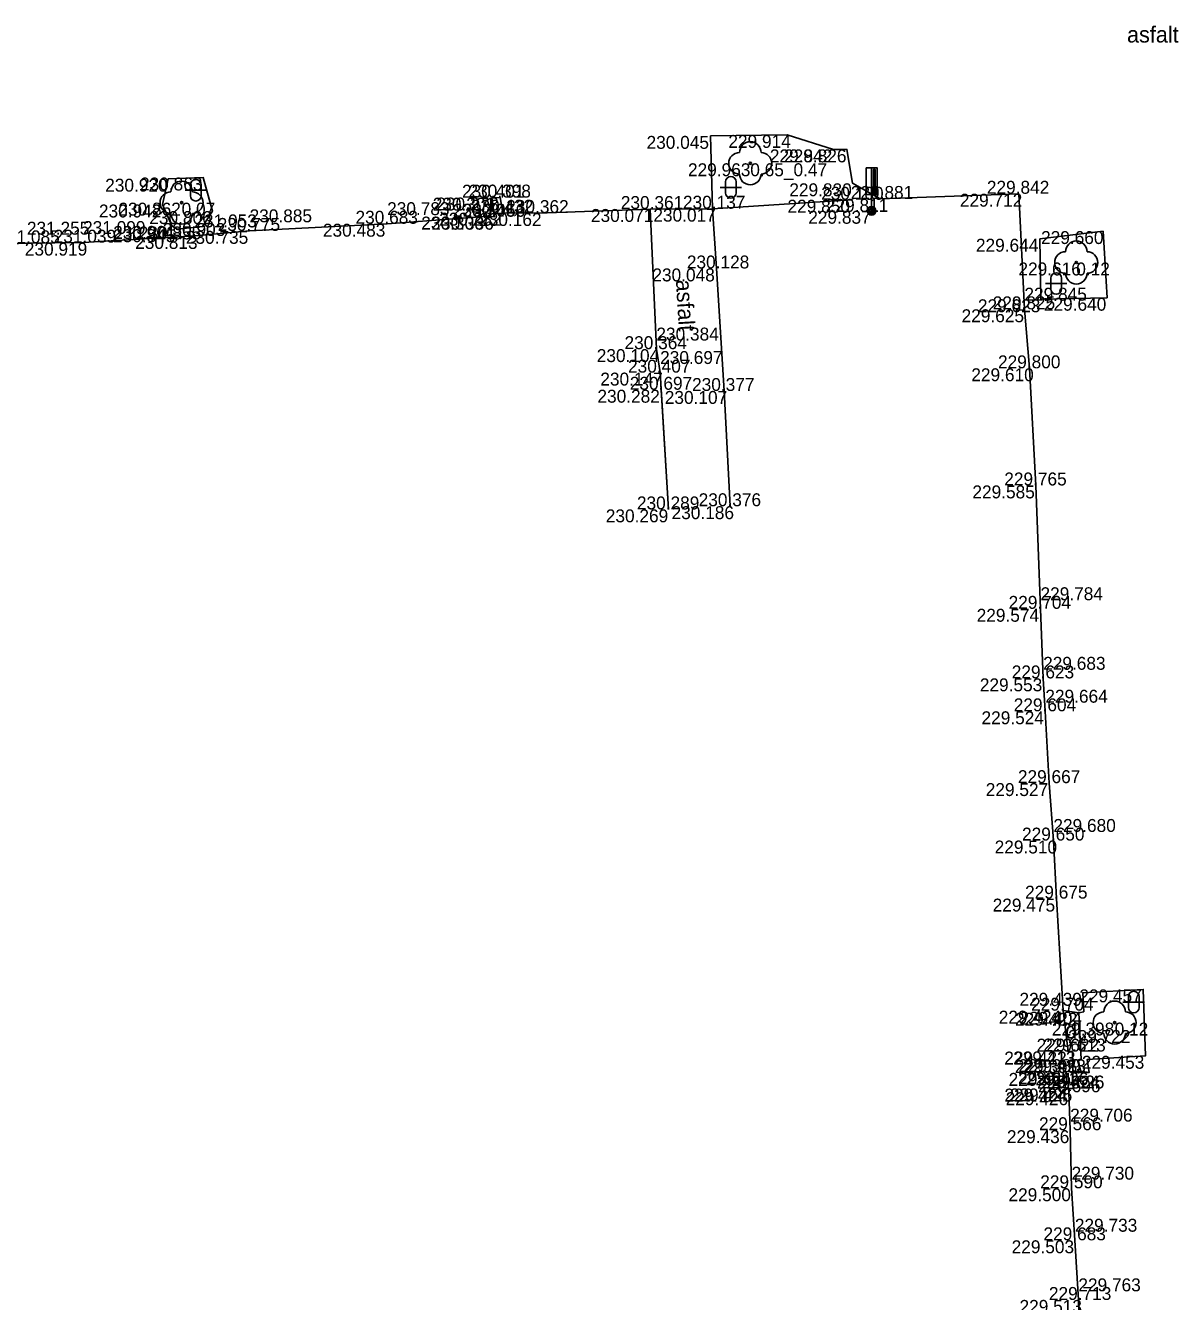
# Model space of a CAD drawing. Extents: x -599516 to -599132, y -1163668 to -1163119.
# Drawn here: x -599458.95 to -599432.17, y -1163270.22 to -1163240.6 of the extents above; entities that cross this region are included whole.
import ezdxf

# ---------------------------------------------------------------- set-up
doc = ezdxf.new("R2010")
doc.units = 0
for name, color, linetype in [('Bod-oznac1', 7, 'Continuous'), ('Bod-oznac2', 7, 'Continuous'), ('Bod-oznac3', 7, 'Continuous'), ('Bod-vyska1', 7, 'Continuous'), ('Bod-vyska2', 7, 'Continuous'), ('Bod-vyska3', 7, 'Continuous'), ('Z_cela-hrobu-dolni-linie', 7, 'Continuous'), ('Z_cela-hrobu-horni-linie', 7, 'Continuous'), ('Z_chodnik', 7, 'Continuous'), ('Z_komunikace', 7, 'Continuous'), ('Z_kultury-znacky', 7, 'Continuous'), ('Z_nove-stromy-prumer-kmene', 7, 'Continuous'), ('Z_obvod-kmene-spodek-ve-vysce1_2m', 7, 'Continuous'), ('Z_popis-budov-povrchu', 7, 'Continuous'), ('Z_stromy-kere', 7, 'Continuous'), ('Z_stromy-nove-vysazene', 7, 'Continuous'), ('Z_terenni-hrana', 7, 'Continuous'), ('Z_znacky-ostatni-orientacni-sloupek', 7, 'Continuous'), ('Z_zpevnene-plochy', 7, 'Continuous')]:
    doc.layers.add(name, color=color, linetype=linetype)

msp = doc.modelspace()

# ---------------------------------------------------------------- linework, layer by layer
at = {"layer": 'Bod-oznac1'}
for p, q in [((-599443.036, -1163243.164), (-599443.036, -1163243.164)), ((-599441.259, -1163243.142), (-599441.259, -1163243.142)), ((-599440.18, -1163243.477), (-599440.18, -1163243.477)), ((-599439.872, -1163243.478), (-599439.872, -1163243.478)), ((-599442.116, -1163243.8), (-599442.116, -1163243.8)), ((-599455.633, -1163244.158), (-599455.633, -1163244.158)), ((-599454.822, -1163244.13), (-599454.822, -1163244.13)), ((-599439.741, -1163244.265), (-599439.741, -1163244.265)), ((-599448.118, -1163244.598), (-599448.118, -1163244.598)), ((-599447.927, -1163244.595), (-599447.927, -1163244.595)), ((-599435.88, -1163244.507), (-599435.88, -1163244.507)), ((-599455.765, -1163244.757), (-599455.765, -1163244.757)), ((-599455.324, -1163244.714), (-599455.324, -1163244.714)), ((-599444.441, -1163244.861), (-599444.441, -1163244.861)), ((-599442.991, -1163244.854), (-599442.991, -1163244.854)), ((-599439.784, -1163244.647), (-599439.784, -1163244.647)), ((-599439.297, -1163244.903), (-599439.297, -1163244.903)), ((-599439.098, -1163244.627), (-599439.098, -1163244.627)), ((-599454.609, -1163244.91), (-599454.609, -1163244.91)), ((-599450.551, -1163245.203), (-599450.551, -1163245.203)), ((-599448.292, -1163245.037), (-599448.292, -1163245.037)), ((-599448.055, -1163245.041), (-599448.055, -1163245.041)), ((-599447.861, -1163244.946), (-599447.861, -1163244.946)), ((-599447.05, -1163244.955), (-599447.05, -1163244.955)), ((-599455.551, -1163245.254), (-599455.551, -1163245.254)), ((-599455.427, -1163245.331), (-599455.427, -1163245.331)), ((-599455.027, -1163245.487), (-599455.027, -1163245.487)), ((-599454.84, -1163245.267), (-599454.84, -1163245.267)), ((-599453.745, -1163245.369), (-599453.745, -1163245.369)), ((-599433.916, -1163245.374), (-599433.916, -1163245.374)), ((-599458.917, -1163245.657), (-599458.917, -1163245.657)), ((-599457.613, -1163245.642), (-599457.613, -1163245.642)), ((-599435.394, -1163245.552), (-599435.394, -1163245.552)), ((-599442.901, -1163246.241), (-599442.901, -1163246.241)), ((-599434.544, -1163246.103), (-599434.544, -1163246.103)), ((-599435.37, -1163246.957), (-599435.37, -1163246.957)), ((-599433.829, -1163246.922), (-599433.829, -1163246.922)), ((-599435.749, -1163247.189), (-599435.749, -1163247.189)), ((-599444.297, -1163248.114), (-599444.297, -1163248.114)), ((-599444.21, -1163248.659), (-599444.21, -1163248.659)), ((-599435.629, -1163248.559), (-599435.629, -1163248.559)), ((-599444.186, -1163249.057), (-599444.186, -1163249.057)), ((-599442.726, -1163249.085), (-599442.726, -1163249.085)), ((-599435.487, -1163251.278), (-599435.487, -1163251.278)), ((-599444.015, -1163251.834), (-599444.015, -1163251.834)), ((-599442.58, -1163251.76), (-599442.58, -1163251.76)), ((-599435.375, -1163254.142), (-599435.375, -1163254.142)), ((-599435.314, -1163255.757), (-599435.314, -1163255.757)), ((-599435.263, -1163256.521), (-599435.263, -1163256.521)), ((-599435.175, -1163258.188), (-599435.175, -1163258.188)), ((-599435.076, -1163259.521), (-599435.076, -1163259.521)), ((-599435.003, -1163260.869), (-599435.003, -1163260.869)), ((-599434.394, -1163263.056), (-599434.394, -1163263.056)), ((-599432.99, -1163262.976), (-599432.99, -1163262.976)), ((-599434.852, -1163263.47), (-599434.852, -1163263.47)), ((-599434.487, -1163263.517), (-599434.487, -1163263.517)), ((-599434.372, -1163263.494), (-599434.372, -1163263.494)), ((-599433.653, -1163263.747), (-599433.653, -1163263.747)), ((-599434.736, -1163264.42), (-599434.736, -1163264.42)), ((-599434.633, -1163264.418), (-599434.633, -1163264.418)), ((-599434.513, -1163264.62), (-599434.513, -1163264.62)), ((-599434.43, -1163264.597), (-599434.43, -1163264.597)), ((-599434.291, -1163264.602), (-599434.291, -1163264.602)), ((-599432.933, -1163264.518), (-599432.933, -1163264.518)), ((-599434.623, -1163264.915), (-599434.623, -1163264.915)), ((-599434.439, -1163264.871), (-599434.439, -1163264.871)), ((-599434.244, -1163264.904), (-599434.244, -1163264.904)), ((-599434.721, -1163265.279), (-599434.721, -1163265.279)), ((-599434.617, -1163265.276), (-599434.617, -1163265.276)), ((-599434.714, -1163265.364), (-599434.714, -1163265.364)), ((-599434.686, -1163266.245), (-599434.686, -1163266.245)), ((-599434.653, -1163267.593), (-599434.653, -1163267.593)), ((-599434.577, -1163268.801), (-599434.577, -1163268.801)), ((-599434.496, -1163270.185), (-599434.496, -1163270.185))]:
    msp.add_line(p, q, dxfattribs=at)
at = {"layer": 'Bod-oznac2'}
for p, q in [((-599448.118, -1163244.598), (-599448.118, -1163244.598)), ((-599447.927, -1163244.595), (-599447.927, -1163244.595)), ((-599435.88, -1163244.507), (-599435.88, -1163244.507)), ((-599444.441, -1163244.861), (-599444.441, -1163244.861)), ((-599442.991, -1163244.854), (-599442.991, -1163244.854)), ((-599439.784, -1163244.647), (-599439.784, -1163244.647)), ((-599439.098, -1163244.627), (-599439.098, -1163244.627)), ((-599450.551, -1163245.203), (-599450.551, -1163245.203)), ((-599448.292, -1163245.037), (-599448.292, -1163245.037)), ((-599448.055, -1163245.041), (-599448.055, -1163245.041)), ((-599447.861, -1163244.946), (-599447.861, -1163244.946)), ((-599447.05, -1163244.955), (-599447.05, -1163244.955)), ((-599455.027, -1163245.487), (-599455.027, -1163245.487)), ((-599453.745, -1163245.369), (-599453.745, -1163245.369)), ((-599458.917, -1163245.657), (-599458.917, -1163245.657)), ((-599457.613, -1163245.642), (-599457.613, -1163245.642)), ((-599442.901, -1163246.241), (-599442.901, -1163246.241)), ((-599435.749, -1163247.189), (-599435.749, -1163247.189)), ((-599444.297, -1163248.114), (-599444.297, -1163248.114)), ((-599444.21, -1163248.659), (-599444.21, -1163248.659)), ((-599435.629, -1163248.559), (-599435.629, -1163248.559)), ((-599444.186, -1163249.057), (-599444.186, -1163249.057)), ((-599442.726, -1163249.085), (-599442.726, -1163249.085)), ((-599435.487, -1163251.278), (-599435.487, -1163251.278)), ((-599444.015, -1163251.834), (-599444.015, -1163251.834)), ((-599442.58, -1163251.76), (-599442.58, -1163251.76)), ((-599435.375, -1163254.142), (-599435.375, -1163254.142)), ((-599435.314, -1163255.757), (-599435.314, -1163255.757)), ((-599435.263, -1163256.521), (-599435.263, -1163256.521)), ((-599435.175, -1163258.188), (-599435.175, -1163258.188)), ((-599435.076, -1163259.521), (-599435.076, -1163259.521)), ((-599435.003, -1163260.869), (-599435.003, -1163260.869)), ((-599434.852, -1163263.47), (-599434.852, -1163263.47)), ((-599434.736, -1163264.42), (-599434.736, -1163264.42)), ((-599434.633, -1163264.418), (-599434.633, -1163264.418)), ((-599434.721, -1163265.279), (-599434.721, -1163265.279)), ((-599434.617, -1163265.276), (-599434.617, -1163265.276)), ((-599434.714, -1163265.364), (-599434.714, -1163265.364)), ((-599434.686, -1163266.245), (-599434.686, -1163266.245)), ((-599434.653, -1163267.593), (-599434.653, -1163267.593)), ((-599434.577, -1163268.801), (-599434.577, -1163268.801)), ((-599434.496, -1163270.185), (-599434.496, -1163270.185))]:
    msp.add_line(p, q, dxfattribs=at)
at = {"layer": 'Bod-oznac3'}
for p, q in [((-599450.551, -1163245.203), (-599450.551, -1163245.203)), ((-599455.027, -1163245.487), (-599455.027, -1163245.487)), ((-599453.745, -1163245.369), (-599453.745, -1163245.369)), ((-599458.917, -1163245.657), (-599458.917, -1163245.657)), ((-599457.613, -1163245.642), (-599457.613, -1163245.642)), ((-599435.749, -1163247.189), (-599435.749, -1163247.189)), ((-599444.297, -1163248.114), (-599444.297, -1163248.114)), ((-599444.21, -1163248.659), (-599444.21, -1163248.659)), ((-599435.375, -1163254.142), (-599435.375, -1163254.142)), ((-599435.314, -1163255.757), (-599435.314, -1163255.757)), ((-599435.263, -1163256.521), (-599435.263, -1163256.521)), ((-599435.076, -1163259.521), (-599435.076, -1163259.521)), ((-599434.736, -1163264.42), (-599434.736, -1163264.42)), ((-599434.686, -1163266.245), (-599434.686, -1163266.245)), ((-599434.653, -1163267.593), (-599434.653, -1163267.593)), ((-599434.577, -1163268.801), (-599434.577, -1163268.801)), ((-599434.496, -1163270.185), (-599434.496, -1163270.185))]:
    msp.add_line(p, q, dxfattribs=at)
at = {"layer": 'Z_cela-hrobu-dolni-linie'}
msp.add_line((-599439.784, -1163244.647), (-599442.991, -1163244.854), dxfattribs=at)
msp.add_lwpolyline([(-599434.852, -1163263.47), (-599434.736, -1163264.42), (-599434.633, -1163264.418), (-599434.623, -1163264.915)], dxfattribs=at)
at = {"layer": 'Z_cela-hrobu-horni-linie'}
for points in [[(-599448.055, -1163245.041), (-599448.118, -1163244.598), (-599447.927, -1163244.595), (-599447.861, -1163244.946)], [(-599434.461, -1163271.161), (-599434.496, -1163270.185), (-599434.496, -1163270.185), (-599434.577, -1163268.801), (-599434.577, -1163268.801), (-599434.653, -1163267.593), (-599434.653, -1163267.593), (-599434.686, -1163266.245), (-599434.686, -1163266.245), (-599434.714, -1163265.364), (-599434.721, -1163265.279), (-599434.617, -1163265.276), (-599434.633, -1163264.418), (-599434.736, -1163264.42), (-599434.736, -1163264.42), (-599434.852, -1163263.47), (-599435.003, -1163260.869), (-599435.076, -1163259.521), (-599435.076, -1163259.521), (-599435.175, -1163258.188), (-599435.263, -1163256.521), (-599435.263, -1163256.521), (-599435.314, -1163255.757), (-599435.314, -1163255.757), (-599435.375, -1163254.142), (-599435.375, -1163254.142), (-599435.487, -1163251.278), (-599435.629, -1163248.559), (-599435.749, -1163247.189), (-599435.749, -1163247.189), (-599435.88, -1163244.507), (-599439.098, -1163244.627)], [(-599447.05, -1163244.955), (-599444.441, -1163244.861), (-599444.297, -1163248.114), (-599444.297, -1163248.114), (-599444.21, -1163248.659), (-599444.21, -1163248.659), (-599444.186, -1163249.057), (-599444.186, -1163249.057), (-599444.015, -1163251.834)], [(-599442.901, -1163246.241), (-599442.991, -1163244.854), (-599439.784, -1163244.647)], [(-599448.292, -1163245.037), (-599450.551, -1163245.203), (-599450.551, -1163245.203), (-599453.745, -1163245.369), (-599453.745, -1163245.369), (-599455.027, -1163245.487), (-599455.027, -1163245.487), (-599457.613, -1163245.642), (-599457.613, -1163245.642), (-599458.917, -1163245.657), (-599458.917, -1163245.657), (-599460.261, -1163245.712), (-599461.643, -1163245.798), (-599461.643, -1163245.798), (-599464.3, -1163245.997), (-599464.116, -1163249.178)], [(-599442.58, -1163251.76), (-599442.726, -1163249.085)]]:
    msp.add_lwpolyline(points, dxfattribs=at)
at = {"layer": 'Z_chodnik'}
msp.add_line((-599444.441, -1163244.861), (-599444.297, -1163248.114), dxfattribs=at)
for points in [[(-599442.58, -1163251.76), (-599442.726, -1163249.085), (-599442.901, -1163246.241), (-599442.991, -1163244.854)], [(-599444.297, -1163248.114), (-599444.21, -1163248.659), (-599444.015, -1163251.834)]]:
    msp.add_lwpolyline(points, dxfattribs=at)
at = {"layer": 'Z_komunikace'}
for p, q in [((-599443.036, -1163243.164), (-599442.991, -1163244.854)), ((-599442.991, -1163244.854), (-599444.441, -1163244.861)), ((-599435.394, -1163245.552), (-599433.916, -1163245.374))]:
    msp.add_line(p, q, dxfattribs=at)
for points in [[(-599443.036, -1163243.164), (-599441.259, -1163243.142), (-599440.18, -1163243.477), (-599439.872, -1163243.478), (-599439.741, -1163244.265), (-599439.098, -1163244.627), (-599435.88, -1163244.507), (-599435.749, -1163247.189), (-599435.629, -1163248.559), (-599435.487, -1163251.278), (-599435.375, -1163254.142), (-599435.314, -1163255.757), (-599435.263, -1163256.521), (-599435.175, -1163258.188), (-599435.076, -1163259.521), (-599435.003, -1163260.869), (-599434.852, -1163263.47), (-599434.487, -1163263.517), (-599434.372, -1163263.494), (-599434.394, -1163263.056), (-599432.99, -1163262.976), (-599432.933, -1163264.518), (-599434.291, -1163264.602), (-599434.244, -1163264.904), (-599434.623, -1163264.915), (-599434.617, -1163265.276), (-599434.721, -1163265.279), (-599434.714, -1163265.364), (-599434.686, -1163266.245), (-599434.653, -1163267.593), (-599434.577, -1163268.801), (-599434.496, -1163270.185), (-599434.461, -1163271.161)], [(-599455.427, -1163245.331), (-599455.551, -1163245.254), (-599455.765, -1163244.757), (-599455.633, -1163244.158), (-599454.822, -1163244.13), (-599454.609, -1163244.91), (-599454.84, -1163245.267), (-599455.427, -1163245.331)], [(-599460.261, -1163245.712), (-599458.917, -1163245.657), (-599457.613, -1163245.642), (-599455.027, -1163245.487), (-599453.745, -1163245.369), (-599450.551, -1163245.203), (-599448.292, -1163245.037), (-599448.055, -1163245.041), (-599448.118, -1163244.598), (-599447.927, -1163244.595), (-599447.861, -1163244.946), (-599447.05, -1163244.955), (-599444.441, -1163244.861)], [(-599435.394, -1163245.552), (-599435.37, -1163246.957), (-599433.829, -1163246.922), (-599433.916, -1163245.374)]]:
    msp.add_lwpolyline(points, dxfattribs=at)
at = {"layer": 'Z_kultury-znacky'}
for p, q in [((-599455.119, -1163244.302), (-599455.119, -1163244.552)), ((-599454.869, -1163244.302), (-599454.869, -1163244.552)), ((-599442.692, -1163244.233), (-599442.692, -1163244.483)), ((-599442.442, -1163244.233), (-599442.442, -1163244.483)), ((-599455.244, -1163244.427), (-599454.744, -1163244.427)), ((-599442.817, -1163244.358), (-599442.317, -1163244.358)), ((-599435.261, -1163246.59), (-599434.761, -1163246.59)), ((-599435.136, -1163246.465), (-599435.136, -1163246.715)), ((-599434.886, -1163246.465), (-599434.886, -1163246.715)), ((-599433.46, -1163263.27), (-599432.96, -1163263.27)), ((-599433.335, -1163263.145), (-599433.335, -1163263.395)), ((-599433.085, -1163263.145), (-599433.085, -1163263.395))]:
    msp.add_line(p, q, dxfattribs=at)
for centre, start, end in [((-599454.995, -1163244.302), 0, 180), ((-599442.568, -1163244.233), 0, 180), ((-599454.995, -1163244.552), 180, 0), ((-599442.568, -1163244.483), 180, 0), ((-599435.011, -1163246.465), 0, 180), ((-599435.011, -1163246.715), 180, 0), ((-599433.21, -1163263.146), 0, 180), ((-599433.21, -1163263.396), 180, 0)]:
    msp.add_arc(centre, 0.125, start, end, dxfattribs=at)
at = {"layer": 'Z_stromy-kere'}
msp.add_circle((-599442.116, -1163243.8), 0.025, dxfattribs=at)
for centre, start, end in [((-599442.116, -1163243.55), 0, 180), ((-599442.366, -1163243.8), 90, 270), ((-599441.866, -1163243.8), 270, 90), ((-599442.116, -1163244.05), 180, 0)]:
    msp.add_arc(centre, 0.25, start, end, dxfattribs=at)
at = {"layer": 'Z_stromy-nove-vysazene'}
for centre in [(-599455.324, -1163244.714), (-599434.544, -1163246.103), (-599433.653, -1163263.747)]:
    msp.add_circle(centre, 0.025, dxfattribs=at)
for centre, start, end in [((-599455.324, -1163244.464), 0, 180), ((-599455.574, -1163244.714), 90, 270), ((-599455.074, -1163244.714), 270, 90), ((-599455.324, -1163244.964), 180, 0), ((-599434.544, -1163245.853), 0, 180), ((-599434.794, -1163246.103), 90, 270), ((-599434.294, -1163246.103), 270, 90), ((-599434.544, -1163246.353), 180, 0), ((-599433.653, -1163263.497), 0, 180), ((-599433.903, -1163263.747), 90, 270), ((-599433.403, -1163263.747), 270, 90), ((-599433.653, -1163263.997), 180, 0)]:
    msp.add_arc(centre, 0.25, start, end, dxfattribs=at)
at = {"layer": 'Z_terenni-hrana'}
msp.add_lwpolyline([(-599434.623, -1163264.915), (-599434.439, -1163264.871), (-599434.244, -1163264.904)], dxfattribs=at)
at = {"layer": 'Z_znacky-ostatni-orientacni-sloupek'}
for p, q in [((-599439.422, -1163243.903), (-599439.422, -1163244.528)), ((-599439.422, -1163243.903), (-599439.297, -1163243.903)), ((-599439.422, -1163244.528), (-599439.297, -1163244.528)), ((-599439.297, -1163244.528), (-599439.297, -1163244.803))]:
    msp.add_line(p, q, dxfattribs=at)
for points in [[(-599439.297, -1163244.528), (-599439.172, -1163244.528), (-599439.172, -1163243.903), (-599439.297, -1163243.903)], [(-599439.255, -1163244.485), (-599439.215, -1163244.485), (-599439.215, -1163243.945), (-599439.255, -1163243.945)]]:
    msp.add_lwpolyline(points, close=True, dxfattribs=at)
for radius in [0.1, 0.065, 0.03]:
    msp.add_circle((-599439.297, -1163244.903), radius, dxfattribs=at)
at = {"layer": 'Z_zpevnene-plochy'}
msp.add_lwpolyline([(-599434.487, -1163263.517), (-599434.43, -1163264.597), (-599434.513, -1163264.62), (-599434.439, -1163264.871)], dxfattribs=at)

# ---------------------------------------------------------------- texts
at = {"layer": 'Bod-vyska1'}
for s, p in [('230.045', (-599444.525, -1163243.464)), ('229.914', (-599442.625, -1163243.442)), ('229.842', (-599441.661, -1163243.777)), ('229.826', (-599441.331, -1163243.778)), ('229.963', (-599443.563, -1163244.1)), ('230.920', (-599457.099, -1163244.458)), ('230.863', (-599456.29, -1163244.43)), ('229.830', (-599441.209, -1163244.565)), ('230.301', (-599449.492, -1163244.898)), ('230.278', (-599449.408, -1163244.895)), ('229.712', (-599437.248, -1163244.807)), ('230.942', (-599457.245, -1163245.057)), ('230.862', (-599456.792, -1163245.014)), ('230.806', (-599456.075, -1163245.21)), ('230.071', (-599445.817, -1163245.161)), ('230.017', (-599444.367, -1163245.154)), ('229.850', (-599441.252, -1163244.947)), ('229.837', (-599440.769, -1163245.203)), ('229.811', (-599440.36, -1163244.927)), ('230.483', (-599452.042, -1163245.503)), ('230.306', (-599449.758, -1163245.337)), ('230.336', (-599449.523, -1163245.341)), ('230.282', (-599449.341, -1163245.246)), ('230.162', (-599448.414, -1163245.255)), ('230.845', (-599456.918, -1163245.631)), ('230.901', (-599456.913, -1163245.554)), ('230.813', (-599456.403, -1163245.787)), ('230.855', (-599456.32, -1163245.567)), ('230.735', (-599455.226, -1163245.669)), ('229.660', (-599435.362, -1163245.674)), ('230.919', (-599458.966, -1163245.942)), ('229.644', (-599436.875, -1163245.852)), ('230.048', (-599444.39, -1163246.541)), ('229.616', (-599435.888, -1163246.403)), ('229.623', (-599436.829, -1163247.257)), ('229.640', (-599435.297, -1163247.222)), ('229.625', (-599437.208, -1163247.489)), ('230.104', (-599445.682, -1163248.414)), ('230.147', (-599445.599, -1163248.959)), ('229.610', (-599436.982, -1163248.859)), ('230.282', (-599445.666, -1163249.357)), ('230.107', (-599444.102, -1163249.385)), ('229.585', (-599436.957, -1163251.578)), ('230.269', (-599445.472, -1163252.134)), ('230.186', (-599443.944, -1163252.06)), ('229.574', (-599436.858, -1163254.442)), ('229.553', (-599436.784, -1163256.057)), ('229.524', (-599436.745, -1163256.821)), ('229.527', (-599436.647, -1163258.488)), ('229.510', (-599436.44, -1163259.821)), ('229.475', (-599436.486, -1163261.169)), ('229.457', (-599434.473, -1163263.276)), ('229.439', (-599435.864, -1163263.356)), ('229.424', (-599436.345, -1163263.77)), ('229.422', (-599435.968, -1163263.817)), ('229.404', (-599435.863, -1163263.794)), ('229.398', (-599435.112, -1163264.047)), ('229.422', (-599436.217, -1163264.72)), ('229.413', (-599436.011, -1163264.718)), ('229.395', (-599435.972, -1163264.92)), ('229.389', (-599435.889, -1163264.897)), ('229.423', (-599435.772, -1163264.902)), ('229.453', (-599434.414, -1163264.818)), ('229.424', (-599436.116, -1163265.215)), ('229.356', (-599435.898, -1163265.171)), ('229.426', (-599435.714, -1163265.204)), ('229.424', (-599436.214, -1163265.579)), ('229.426', (-599436.087, -1163265.576)), ('229.426', (-599436.184, -1163265.664)), ('229.436', (-599436.156, -1163266.545)), ('229.500', (-599436.119, -1163267.893)), ('229.503', (-599436.045, -1163269.101)), ('229.513', (-599435.862, -1163270.485))]:
    msp.add_text(s, height=0.3, dxfattribs=at).set_placement(p)
at = {"layer": 'Bod-vyska2'}
for s, p in [('230.401', (-599448.811, -1163244.598)), ('230.398', (-599448.661, -1163244.595)), ('229.842', (-599436.621, -1163244.507)), ('230.361', (-599445.123, -1163244.861)), ('230.137', (-599443.68, -1163244.854)), ('230.100', (-599440.47, -1163244.647)), ('229.881', (-599439.781, -1163244.627)), ('230.683', (-599451.285, -1163245.203)), ('230.706', (-599449.026, -1163245.037)), ('230.456', (-599448.795, -1163245.041)), ('230.432', (-599448.606, -1163244.946)), ('230.362', (-599447.784, -1163244.955)), ('230.903', (-599455.76, -1163245.487)), ('230.775', (-599454.487, -1163245.369)), ('231.085', (-599459.605, -1163245.657)), ('231.039', (-599458.295, -1163245.642)), ('230.128', (-599443.589, -1163246.241)), ('229.825', (-599436.484, -1163247.189)), ('230.364', (-599445.037, -1163248.114)), ('230.407', (-599444.955, -1163248.659)), ('229.800', (-599436.362, -1163248.559)), ('230.697', (-599444.915, -1163249.057)), ('230.377', (-599443.468, -1163249.085)), ('229.765', (-599436.217, -1163251.278)), ('230.289', (-599444.749, -1163251.834)), ('230.376', (-599443.315, -1163251.76)), ('229.704', (-599436.116, -1163254.142)), ('229.623', (-599436.043, -1163255.757)), ('229.604', (-599435.997, -1163256.521)), ('229.667', (-599435.9, -1163258.188)), ('229.650', (-599435.804, -1163259.521)), ('229.675', (-599435.733, -1163260.869)), ('229.704', (-599435.593, -1163263.47)), ('229.622', (-599435.465, -1163264.42)), ('229.613', (-599435.31, -1163264.418)), ('229.624', (-599435.456, -1163265.279)), ('229.626', (-599435.341, -1163265.276)), ('229.696', (-599435.432, -1163265.364)), ('229.566', (-599435.41, -1163266.245)), ('229.590', (-599435.381, -1163267.593)), ('229.683', (-599435.306, -1163268.801)), ('229.713', (-599435.18, -1163270.185))]:
    msp.add_text(s, height=0.3, dxfattribs=at).set_placement(p)
at = {"layer": 'Bod-vyska3'}
for s, p in [('230.885', (-599453.745, -1163245.169)), ('230.783', (-599450.551, -1163245.003)), ('231.255', (-599458.917, -1163245.457)), ('231.099', (-599457.613, -1163245.442)), ('231.053', (-599455.027, -1163245.287)), ('229.845', (-599435.749, -1163246.989)), ('230.384', (-599444.297, -1163247.914)), ('230.697', (-599444.21, -1163248.459)), ('229.784', (-599435.375, -1163253.942)), ('229.683', (-599435.314, -1163255.557)), ('229.664', (-599435.263, -1163256.321)), ('229.680', (-599435.076, -1163259.321)), ('229.722', (-599434.736, -1163264.22)), ('229.706', (-599434.686, -1163266.045)), ('229.730', (-599434.653, -1163267.393)), ('229.733', (-599434.577, -1163268.601)), ('229.763', (-599434.496, -1163269.985))]:
    msp.add_text(s, height=0.3, dxfattribs=at).set_placement(p)
at = {"layer": 'Z_nove-stromy-prumer-kmene'}
for s, p in [('0.07', (-599455.324, -1163245.014)), ('0.12', (-599434.544, -1163246.403)), ('0.12', (-599433.653, -1163264.047))]:
    msp.add_text(s, height=0.3, dxfattribs=at).set_placement(p)
at = {"layer": 'Z_obvod-kmene-spodek-ve-vysce1_2m'}
msp.add_text('0.65_0.47', height=0.3, dxfattribs=at).set_placement((-599442.116, -1163244.1))
at = {"layer": 'Z_popis-budov-povrchu'}
for s, p in [('asfalt', (-599433.365, -1163240.997)), ('dl.', (-599434.801, -1163264.115))]:
    msp.add_text(s, height=0.375, dxfattribs=at).set_placement(p)
msp.add_text('asfalt', height=0.375, rotation=273.4503, dxfattribs=at).set_placement((-599443.844, -1163246.509))

doc.saveas('drawing.dxf')
